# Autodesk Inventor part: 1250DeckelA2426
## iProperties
Category: PARTsolutions
Created: 2011-08
Part Number: 1250DeckelA2426
Catalog Web Link: www.cadenas.de
Description: 1250 Deckel Aussen - Deckel Außen
Document SubType Name: Modeling
Designer: PARTsolutions
Density: 1 g/cm^3
Mass: 143.68 g
Surface Area: 1098.78 cm^2
Volume: 143.68 cm^3
NB: 1250DeckelA2426
NN: 1250 Deckel Aussen
NT: Deckel Außen
NBSYN: 1250DeckelA2426
LINA: 1250DeckelA2426
BEST: 1250DeckelA
BI: 242
BIMIN: 101.000
BIMAX: 751.000
BKMIN: 150.000
BKMAX: 800.000
STEGV: 6
BST: 267.000
KT: DUMMY
SUPPLIER: Kabelschlepp
ARTICLENO: 1250DeckelA2426
BOMINFO: 1250DeckelA2426
CREATOR: CADENAS GmbH
PSOL_IDENT_0: {\\10.0.0.251\ps_data\23d-libs\kabelschlepp\4_eketten_st\parts\1250_deckel_a.prj},192 {VTYP=3D},{NB=
PSOL_IDENT_1: 1250DeckelA2426},{LINA=1250DeckelA2426},{NN=1250 Deckel Aussen},{DATE=21.04.2010 06:15:58},{GEOMDATE
PSOL_IDENT_2: =21.04.2010 06:15:00},{VERSION=},{LINEID=10},{LINESUBID=-1},{WBVAR=BI,STEGV}  {NB=1250DeckelA2426},{
PSOL_IDENT_3: LINA=1250DeckelA2426},{KT=DUMMY},{BEST=1250DeckelA},{BI=242},{BIMIN=101},{BIMAX=751},{BKMIN=150},{BK
PSOL_IDENT_4: MAX=800},{STEGV=6},{BST=267}
Title: 1250DeckelA2426
Author: Cadenas PARTsolutions
Comments: Deckel Außen
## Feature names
1. Extrusion1
2. Extrusion2
3. Extrusion3
4. Extrusion4
